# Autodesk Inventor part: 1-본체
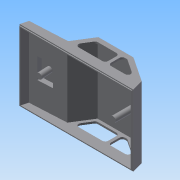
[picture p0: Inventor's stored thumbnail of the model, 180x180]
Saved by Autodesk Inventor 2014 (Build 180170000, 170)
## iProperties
Created: 2015-05
Part Number: 1-본체
Material: Generic
Document SubType Name: Modeling
Designer: Administrator
Density: 1 g/cm^3
Appearance: Default
Author: Administrator
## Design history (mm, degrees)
sketch "스케치1"
  geometry: L1 (-61, 0)-(61, 0); L2 (61, 11)-(57.412, 13.392); L3 (-58.588, 9)-(-19, 11.075); L4 (-6.549, 31)-(-19, 11.075); L5 (-61, 0)-(-58.588, 9); L6 (57.412, 13.392)-(61, 0); L7 (-6.549, 31)-(31, 31); L8 (61, 0)-(61, 13.212); L9 (57.412, 13.392)-(31, 31); 2 further points
  constraints: 18 end point, 1 coincident, 1 horizontal, 1 midpoint, 1 parallel, 1 perpendicular, 1 point on line
  dimensions: "d0" = 122 distance of L1.start L1.end; "d4" = 31 distance from line of L1 L7.end; "d9" = 9 vertical distance of L1.start L3.start; "d19" = 3 deg angle of L1 L3; "d21" = 125 deg angle of L3 L4; "d22" = 105 deg angle of L1 L5; "d23" = 105 deg angle of L1 L6; "d37" = 30 horizontal distance of L1.end L7.end; "d38" = 42 horizontal distance of L3.end L1.start; "d41" = 20 vertical distance of L7.end L2.start; "d42" = 31.74272 distance of L2.end L7.end
extrude "돌출1" new body sketch "스케치1" distance "d24" = 76; taper "d25" = 0 deg
feature "쉘1" dims "d26" = 2
sketch "스케치2"
  geometry: L1 (31, 31)-(-6.549, 31) reference; L2 (-61, 0)-(61, 0) reference; L3 (57.412, 13.392)-(31, 31) reference; L4 (-6.549, 31)-(-19, 11.075) reference; L5 (30.242, 25.496)-(43.742, 16.496); L6 (28.578, 26)-(26.986, 26); L7 (42.078, 11)-(26.986, 11); L8 (23.986, 14)-(23.986, 23); L9 (17.849, 11)-(-7.739, 11); L10 (-10.283, 15.59)-(-4.659, 24.59); L11 (-2.115, 26)-(17.849, 26); L12 (20.849, 23)-(20.849, 14); A1 r 3 centre (-2.115, 23) between (-2.115, 26) and (-4.659, 24.59); A2 r 3 centre (-7.739, 14) between (-10.283, 15.59) and (-7.739, 11); A3 r 3 centre (17.849, 23) between (20.849, 23) and (17.849, 26); A4 r 3 centre (17.849, 14) between (17.849, 11) and (20.849, 14); A5 r 3 centre (26.986, 23) between (26.986, 26) and (23.986, 23); A6 r 3 centre (26.986, 14) between (23.986, 14) and (26.986, 11); A7 r 3 centre (28.578, 23) between (30.242, 25.496) and (28.578, 26); A8 r 3 centre (42.078, 14) between (42.078, 11) and (43.742, 16.496); 6 further points
  constraints: 16 end point, 16 point on circle, 16 tangent, 10 point on line, 8 centre point, 7 equal radius, 5 parallel, 3 perpendicular
  dimensions: "d64" = 5 distance between parallel lines of L3 L5; "d65" = 5 distance between parallel lines of L1 L6; "d66" = 15 distance between parallel lines of L6 L7; "d67" = 28 distance of point (51.986, 11) point (23.986, 11); "d68" = 34 distance of point (20.849, 11) point (-13.151, 11); "d69" = 5 distance between parallel lines of L10 L4; "d70" = 15 distance from line of L9 point (-3.778, 26); "d71" = 5 distance between parallel lines of L11 L1; "d72" = 3 radius of A1
extrude "돌출2" cut sketch "스케치2" stored distance "d44" = 10; taper "d45" = 0 deg
sketch "스케치4"
  geometry: L1 (0, 76)-(0, 0) reference; L2 (28.121, 25)-(8.121, 25); L3 (8.121, 25)-(8.121, 51); L4 (8.121, 51)-(28.121, 51); L5 (28.121, 51)-(28.121, 25); L6 (28.121, 25)-(8.121, 51); L7 (8.121, 25)-(28.121, 51); L8 (-2.879, 76)-(-2.879, 0) reference; 4 further points
  constraints: 12 end point, 4 midpoint, 2 parallel, 1 horizontal, 1 horizontal alignment, 1 perpendicular
  dimensions: "d48" = 20 distance of L3.end L4.end; "d49" = 26 distance of L2.end L3.end; "d50" = 11 distance between parallel lines of L3 L8
extrude "돌출3" join sketch "스케치4" distance "d51" = 5; taper "d52" = 0 deg
feature "쉘2" dims "d53" = 2
sketch "스케치6"
  geometry: L1 (0, 0)-(122, 0) reference; L2 (122, 0)-(122, 76) reference; L3 (0, 76)-(122, 76) reference; L4 (0, 0)-(0, 76) reference; L5 (121, 75)-(121, 1); L6 (121, 1)-(1, 1); L7 (1, 1)-(1, 75); L8 (1, 75)-(121, 75); 1 further point
  constraints: 8 end point, 3 other
  dimensions: "d55" = 1 distance between parallel lines of L8 L3
extrude "돌출4" cut sketch "스케치6" distance "d56" = 1; taper "d57" = 0 deg
sketch "스케치5"
  geometry: L1 (0, 0)-(0, 22) reference; L2 (16, 0)-(0, 0) reference; C1 r 3 at (8, 11); 3 further points
  constraints: 2 midpoint, 1 centre point, 1 horizontal alignment, 1 vertical alignment
  dimensions: "d54" = 6 diameter of C1
extrude "돌출5" join sketch "스케치5" stored distance "d58" = 1; taper "d59" = 0 deg
node "작업 평면3"
sketch "스케치10"
  geometry: L1 (60.732, 76)-(60.732, 0) reference; L2 (60, 1)-(60, 75) reference; C1 r 3 at (39.732, 38); 2 further points
  constraints: 1 centre point, 1 horizontal alignment, 1 midpoint
  dimensions: "d78" = 6 diameter of C1; "d79" = 21 distance from line of C1.centre L1
extrude "돌출8" join sketch "스케치10" stored distance "d80" = 1; taper "d81" = 0 deg
sketch "스케치8"
  geometry: L1 (66.173, 74)-(66.173, -2) reference; L2 (66.173, 36)-(-59.707, 36); C1 r 3 at (5.173, 14); C2 r 3 at (5.173, 58); C3 r 3 at (45.173, 36) reference; 2 further points; 1 other entity
  constraints: 2 centre point, 2 end point, 1 equal radius, 1 horizontal, 1 midpoint, 1 vertical alignment, 2 other
  dimensions: "d73" = 6 diameter of C2; "d74" = 61 distance from line of C2.centre L1; "d75" = 44 distance of C1.centre C2.centre
extrude "돌출7" join sketch "스케치8" stored distance "d76" = 1; taper "d77" = 0 deg
node "작업 평면1"
sketch "스케치9"
  geometry: L1 (36.732, 0)-(36.732, 24.775) reference; L2 (42.732, 0)-(42.732, 20.775) reference; L3 (55.675, 12.146)-(30.394, 29) reference; L4 (48.723, 16.781)-(46.091, 2.619); L5 (46.091, 2.619)-(44.363, 2.94); 1 further point
  constraints: 4 end point, 1 perpendicular, 1 point on line
node "솔리드1"
